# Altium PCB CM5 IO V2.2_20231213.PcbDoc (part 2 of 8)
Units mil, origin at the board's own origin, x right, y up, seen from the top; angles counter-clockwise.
Board outline 6299.61 x 3544.09 mil, 4 copper layers (Top, GND, Power, Bottom), stack 35.4 mil thick; 482 components, 404 nets, 1857 pads, 2731 vias.
Unrouted connection lines stored in the file: 1872.
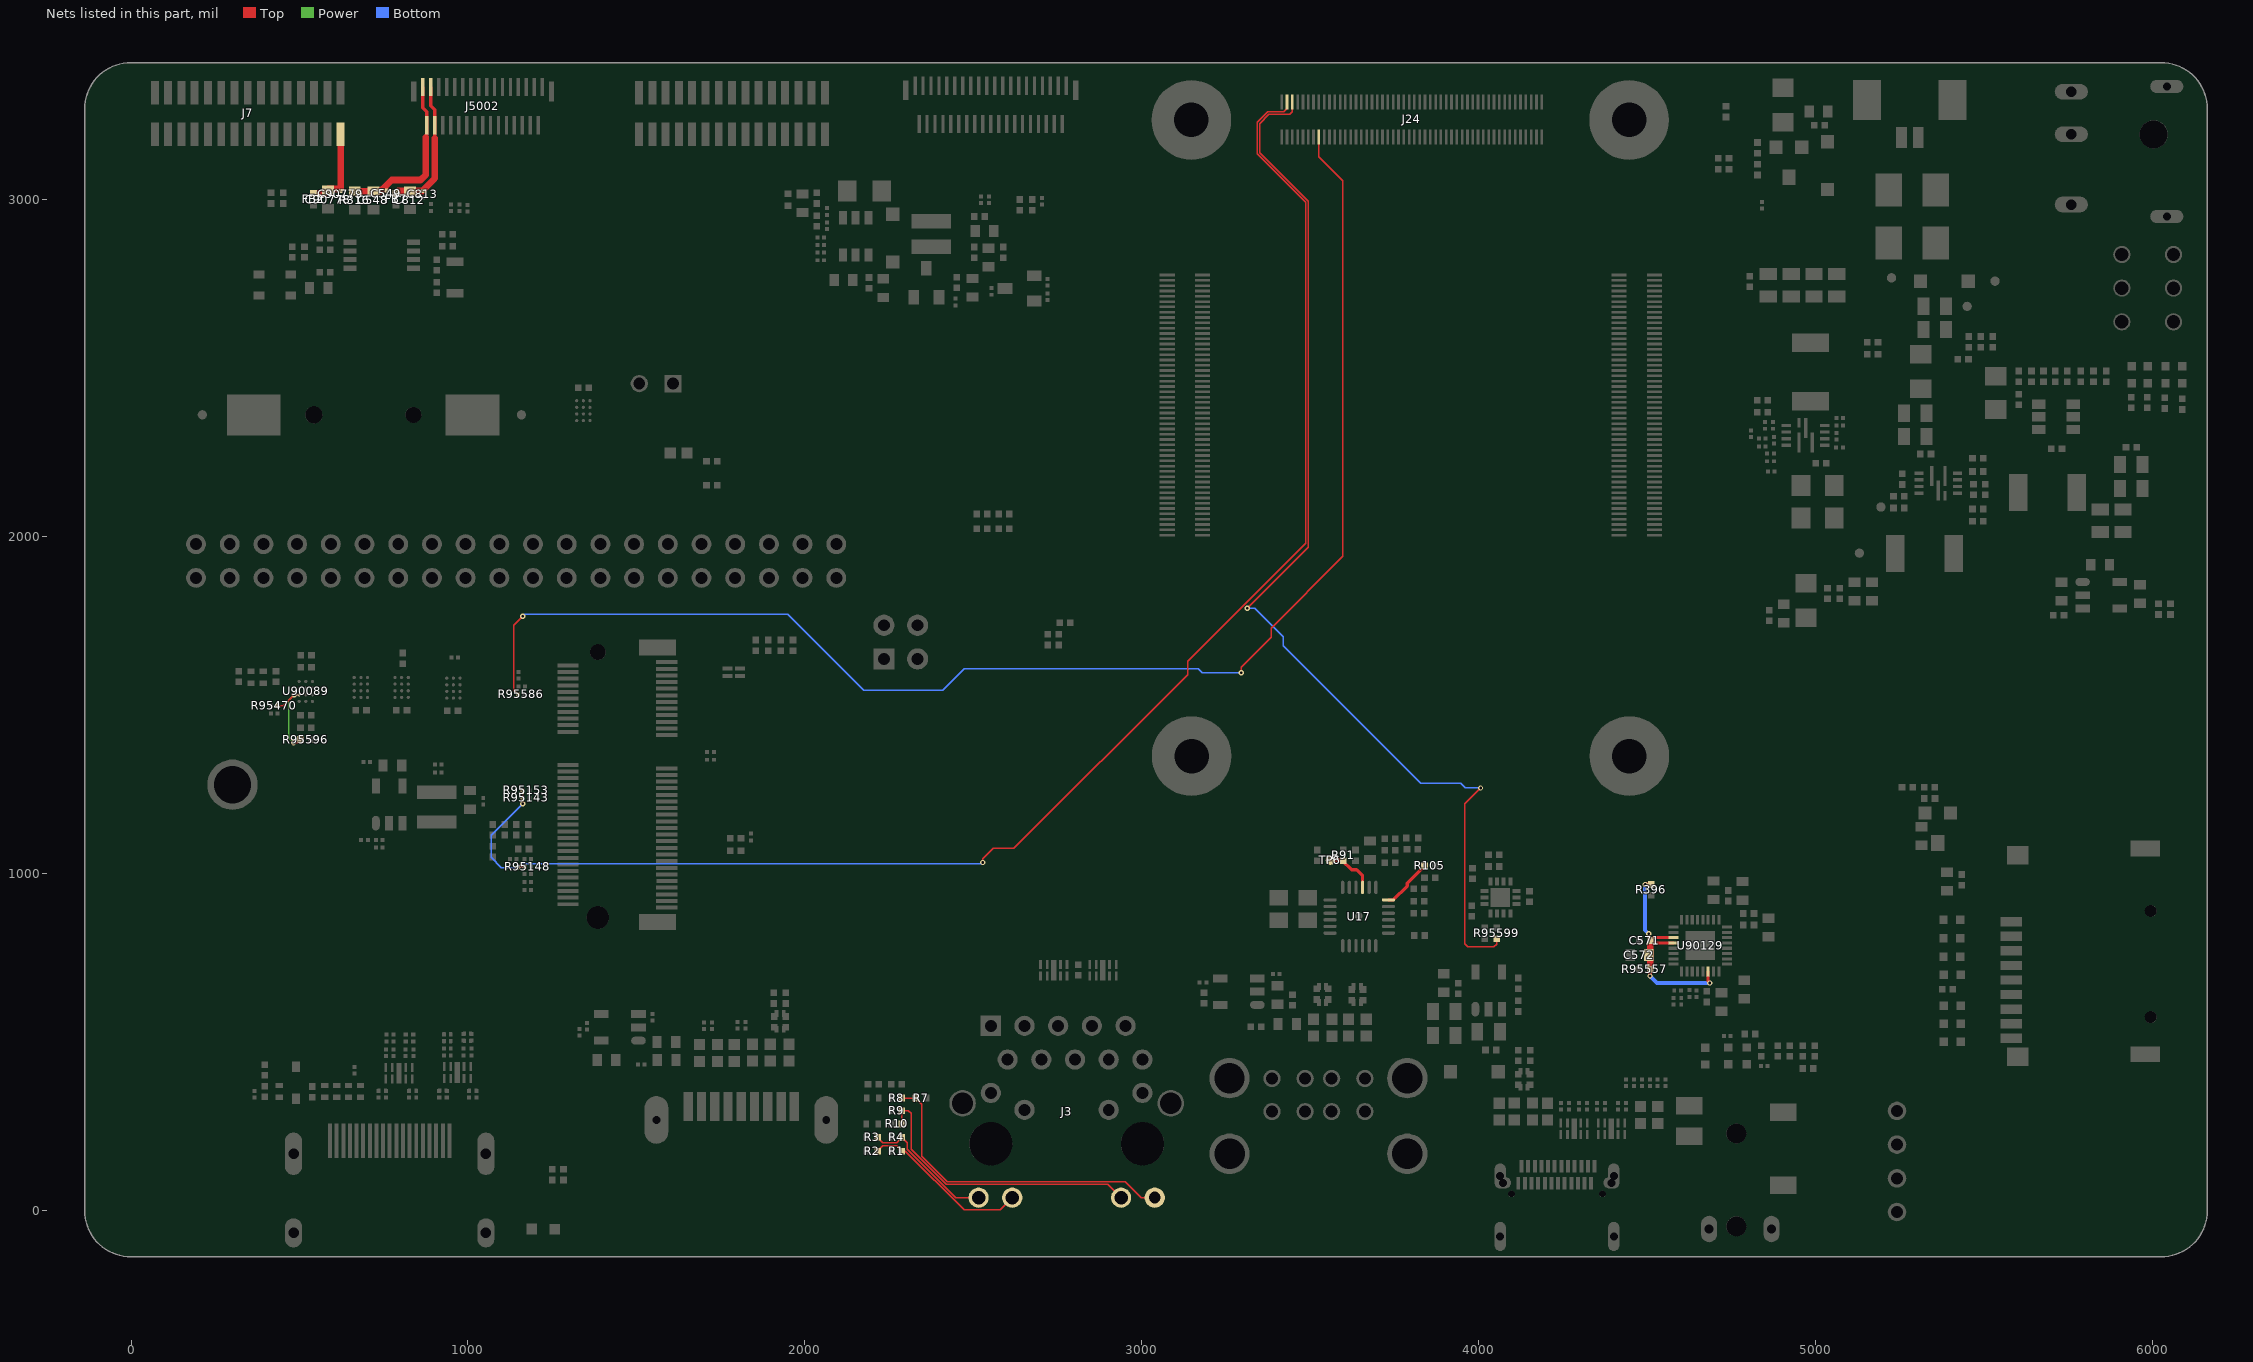
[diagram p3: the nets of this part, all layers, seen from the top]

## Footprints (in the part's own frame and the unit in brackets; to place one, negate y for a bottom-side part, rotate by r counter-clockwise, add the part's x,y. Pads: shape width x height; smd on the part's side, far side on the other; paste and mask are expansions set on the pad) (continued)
SON10_2R50X1R00X0R50 [mm]
  rect 0.2x0.675 smd: 1(-1,-0.437) 2(-0.5,-0.437) 4(0.5,-0.437) 5(1,-0.437) 6(1,0.437) 7(0.5,0.437) 9(-0.5,0.437) 10(-1,0.437)
  rect 0.4x0.775 smd: 3(0,-0.388) 8(0,0.388)
  silkscreen extent -1.46,-1.39 1.25,0.5
SOT23 [mil]
  rect 39x39 smd: 1(-38,-44.53) 2(38,-44.53)
  rect 39.37x47.24 smd: 3(0,44.53)
SOT23-6 [mm]
  rect 0.6x1 smd: 1(-0.95,-1.4) 2(0,-1.4) 3(0.95,-1.4) 4(0.95,1.4) 5(0,1.4) 6(-0.95,1.4)
  silkscreen extent -1.8,-1.9 1.5,0.8
SOT_23 [mm]
  rect 0.8x1.1 smd: 1(-0.95,-1.1) 2(0.95,-1.1) 3(0,1.1)
  silkscreen extent -1.6,-0.9 1.6,0.9
SOT_23_5 [mm]
  oval 1.1x0.6 smd: 1(-1.4,1)
  rect 1.1x0.6 smd: 2(-1.4,0) 3(-1.4,-1) 4(1.4,-1) 5(1.4,1)
  silkscreen extent -0.52,-1.5 0.55,1.5
SOT_23_6 [mm]
  rect 0.7x1 smd mask+0.05: 1(-0.95,-1.3) 2(0,-1.3) 3(0.95,-1.3) 4(0.95,1.3) 5(0,1.3) 6(-0.95,1.3)
  silkscreen extent -1.82,-1.72 1.75,0.7
TF-CKT01-009D [mm]
  rect 1.6x0.7 smd: 1(-10.516,3.2) 2(-10.516,2.1) 3(-10.516,1) 4(-10.516,-0.1) 5(-10.516,-1.2) 6(-10.516,-2.3) 7(-10.516,-3.4) 8(-10.516,-4.5) 9(-10.516,-5.6)
  rect 1.6x1.4 smd: 10(-10.016,-7) 13(-10.016,8.2)
  rect 2.2x1.2 smd: 11(-0.416,-6.8) 12(-0.416,8.7)
  round 0.9 hole 0.9 unplated: 14(0,4) 15(0,-4)
  silkscreen extent -10.52,-6.4 3.98,8.3
TP_0R70 [mm]
  round 0.7 smd: 1(0,0)
  silkscreen extent -0.45,-0.45 0.45,0.45
TYPEC-24PIN-SMD-OK [mm]
  rect 0.3x0.95 smd: A1(1.61,5.29) A2(2.11,5.29) A3(2.61,5.29) A4(3.11,5.29) A5(3.61,5.29) A6(4.11,5.29) A7(4.61,5.29) A8(5.11,5.29) A9(5.61,5.29) A10(6.11,5.29) A11(6.61,5.29) A12(7.11,5.29) B1(6.86,3.99) B2(6.36,3.99) B3(5.86,3.99) B4(5.36,3.99) B5(4.86,3.99) B6(4.36,3.99) B7(3.86,3.99) B8(3.36,3.99) B9(2.86,3.99) B10(2.36,3.99) B11(1.86,3.99) B12(1.36,3.99)
  oval 0.85x1.9 / inner oval 0.85x1.8 / far side oval 1x2.1 hole 0.6 slot 1.5 at 90 deg: E1(0,4.55) E6(8.56,4.55)
  oval 1.2x0.85 / inner oval 1.2x0.85 / far side oval 1.2x0.9 hole 0.6 slot 1 at 0 deg: E2(0.21,4.04) E5(8.38,4.04)
  oval 0.85x2.2 / inner oval 0.85x2.2 / far side oval 1x2.2 hole 0.6 slot 1.9 at 90 deg: E3(0,0)
  oval 0.85x2.2 / inner oval 0.85x2.2 / far side oval 1x2.25 hole 0.6 slot 1.9 at 90 deg: E4(8.56,0)
  round 0.5 hole 0.5: H1(0.85,3.2) H2(7.71,3.2)
  silkscreen extent -0.24,-2.35 8.87,5.55
USB30-L1 [mm]
  rect 0.7x2.2 smd: 1(-3,0) 2(-1,0) 3(1,0) 4(3,0) 5(4,0) 6(2,0) 7(0,0) 8(-2,0) 9(-4,0)
  oval 1.8x3.6 / inner oval 0.7x2.6 / far side oval 1.8x3.6 hole 0.584 slot 2.489 at 90 deg: 10(-6.4,-1) 11(6.4,-1)
  silkscreen extent -9.28,-14.64 9.29,0.92
USB_DUAL [mm]
  round 1.3 / inner round 0.9 / far side round 1.3 hole 0.9: 1(3.18,3.5) 2(3.18,1) 3(3.18,-1) 4(3.18,-3.5) 5(5.68,3.5) 6(5.68,1) 7(5.68,-1) 8(5.68,-3.5)
  round 3.048 / inner round 2.5 / far side round 3.048 hole 2.3: 9(0,6.7)
  round 3.048 / inner round 2.5 / far side round 3.048 hole 2.286: 10(0,-6.7) 11(5.7,6.7) 12(5.7,-6.7)
  silkscreen extent -9.97,-7.52 7.1,7.61
XIAO_4PIN_2D54 [mm]
  round 1.4 hole 0.9: 1(0.01,0) 2(2.55,0) 3(5.09,0) 4(7.63,0)
  silkscreen extent -1.19,-3.3 8.81,2.36

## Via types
v1: diameter 15.75, hole 7.87, Top to Bottom, 2292 vias
v2: diameter 19.68, hole 11.81, Top to Bottom, 439 vias

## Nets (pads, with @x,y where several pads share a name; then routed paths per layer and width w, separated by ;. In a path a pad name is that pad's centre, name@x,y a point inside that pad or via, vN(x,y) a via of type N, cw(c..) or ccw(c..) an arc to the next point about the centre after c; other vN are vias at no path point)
3V3_CAM1: C90778.1 C90779.1 FB2.2 J7.1 | length 256.6
  Top w11.81: C90779.1@622.05,3024.61 622.05,3030.51
  Top w19.68: FB2.2@541.34,3017.72 575.79,3017.72 C90778.1@584.65,3026.57 584.65,3030.51 622.05,3030.51 J7.1@622.05,3192.91
3V3_CAM2: C812.1 C813.1 FB7.2 J5002.28 J5002.29 | length 411
  Top w3.94: C813.1@864.17,3024.61 C813.1@866.14,3024.61
  Top w9.84: J5002.29@889.76,3332.68 889.76,3277.56 901.57,3265.75 J5002.28@901.57,3219.5 901.57,3197.5 901.57,3180.12
  Top w19.68: FB7.2@786.42,3017.72 793.31,3024.61 C812.1@827.76,3024.61 864.17,3024.61 901.57,3062.01 901.57,3180.12
5V_CAM: C548.1 C549.1 J5002.30 J5002.31 R316.2 | length 530
  Top w9.84: J5002.31@866.14,3332.68 866.14,3271.65 877.95,3259.84 J5002.30@877.95,3219.5 877.95,3187.01 875,3184.06
  Top w11.81: 740.65,3024.11 743.6,3024.11 745.08,3025.59 C549.1@757.87,3025.59
  Top w12.99: 755.91,3039.37 756.5,3039.37 757.87,3037.99 C549.1@757.87,3025.59
  Top w19.68: R316.2@663.88,3024.11 C548.1@719,3024.11 740.65,3024.11 755.91,3039.37 773.62,3057.09 859.25,3057.09 875,3072.83 875,3184.06
100M_LED_G+: J3.15 R3.2 R4.1 | length 398.3
  Top w3.94: R3.2@2215.55,216.54 2231.3,200.79 2271.65,200.79 R4.1@2287.4,216.54 2303.15,200.79 2303.15,181.47 2447.45,37.17 J3.15@2515.17,37.17
100M_LED_G-: J3.16 R1.2 R2.1 | length 499.8
  Top w3.94: R2.1@2215.55,175.2 2231.3,190.94 2271.65,190.94 R1.2@2287.4,175.2 2298.29,175.2 2472.5,0.98 2578.99,0.98 J3.16@2615.17,37.17
1000M_LED_Y+: J3.17 R9.2 R10.1 | length 859.3
  Top w3.94: R10.1@2287.4,255.91 R9.2@2287.4,295.28 2307.09,295.28 2314.96,287.4 2314.96,180.79 2418.98,76.77 2898.4,76.77 J3.17@2938.01,37.17
1000M_LED_Y-: J3.18 R7.2 R8.1 | length 963.5
  Top w3.94: R8.1@2287.4,332.68 R7.2@2328.74,332.68 2346.46,314.96 2346.46,160.43 2422.24,84.65 2949.8,84.65 2997.28,37.17 J3.18@3038.01,37.17
AVCC_1V8_CODEC_S0: C571.1 C572.1 R396.1 R95557.2 U90129.3 U90129.4 U90129.14 | length 669.2
  Top w9.06: U90129.4@4576.96,792.94 4515.13,792.94 C571.1@4507.87,800.2 4516.36,808.69 U90129.3@4576.96,808.69 ; U90129.14@4680.3,708.29 4680.3,678.95 v1(4685.04,674.21)
  Top w11.81: v1(4493.11,966.54) R396.1@4511.81,966.54 ; v1(4503.94,819.88) 4503.94,800.2 C571.1@4507.87,800.2 ; v1(4507.87,694.88) R95557.2@4507.87,714.57
  Top w19.68: C572.1@4503.94,756.89 C572.1@4507.87,756.89 ; R95557.2@4507.87,714.57 C572.1@4507.87,756.89 ; C571.1@4507.87,800.2 C572.1@4507.87,756.89
  Bottom w11.81: v1(4493.11,966.54) 4493.11,830.71 v1(4503.94,819.88) ; v1(4507.87,694.88) 4528.54,674.21 v1(4685.04,674.21)
BT_HOST_WAKE: J24.85 R95586.1 | length 4252.4
  Top w3.94: R95586.1@1148.58,1530.5 1135.83,1543.25 1135.83,1736.22 v1(1162.4,1762.8) ; v1(3294.67,1595.1) 3294.67,1611.6 3383.86,1700.79 3383.86,1727.36 3596.46,1939.96 3596.46,3055.09 3525,3126.54 J24.85@3525,3184.65
  Bottom w3.94: v1(1162.4,1762.8) 1168.31,1768.7 1948.57,1768.7 2173.96,1543.31 2408.72,1543.31 2472.69,1607.28 3166.45,1607.28 3178.63,1595.1 v1(3294.67,1595.1)
BT_REG_ON_H: J24.98 R95143.1 R95148.1 R95153.1 | length 4551.8
  Top w3.94: v1(1147.64,1016.73) 1147.64,1019.68 R95148.1@1167.28,1019.67 ; R95153.1@1162.36,1246.05 R95143.1@1162.36,1223.41 v1(1162.4,1205.71) v1(1162.4,1205.71) ; v1(2527.56,1031.5) 2527.56,1042.95 2558.59,1073.97 2620.09,1073.97 3135.54,1589.42 3135.54,1628.5 3485.63,1978.59 3485.63,2991.14 3341.54,3135.24 3341.54,3227.92 3373.46,3259.84 3420.75,3259.84 3430.51,3269.6 J24.98@3430.51,3288.58
  Bottom w3.94: v1(1162.4,1205.71) 1068.9,1112.2 1068.9,1047.24 1099.41,1016.73 v1(1147.64,1016.73) 1159.45,1028.54 2524.61,1028.54 v1(2527.56,1031.5)
BUSJ: R105.2 U17.18 | length 154.1
  Top w9.84: U17.18@3731.49,920.57 3746.25,920.57 3787.4,961.72 3787.4,970.47 R105.2@3838.58,1021.65
CC_INT0_L: J24.96 R95599.1 | length 3244
  Top w3.94: v1(3312.43,1785.87) 3493.5,1966.95 3493.5,2994.4 3349.41,3138.5 3349.41,3224.66 3376.72,3251.97 3438.98,3251.97 3446.26,3259.25 J24.96@3446.26,3288.58 ; 3966.4,781.37 3957.9,789.87 3957.9,1205.93 v1(4004.92,1252.95) ; 3966.41,781.38 4044.6,781.38 4052.78,789.56 R95599.1@4052.78,805.87
  Bottom w3.94: v1(3312.43,1785.87) 3335.19,1785.87 3419.29,1701.77 3419.29,1674.21 3826.77,1266.73 3945.87,1266.73 3959.65,1252.95 v1(4004.92,1252.95)
DRV: R91.2 TP6.1 U17.21 | length 154.4
  Top w9.84: R91.2@3597.44,1037.4 3594.98,1037.4 3622.54,1009.84 3636.81,1009.84 3654.72,991.94 U17.21@3654.72,957.97
  Top w11.81: TP6.1@3559.06,1038.39 3597.44,1038.39 R91.2@3597.44,1037.4
EINT_CTP1: R95470.1 R95596.2 U90089.C1 | length 257.9
  Top w3.94: R95470.1@435.04,1497.05 451.77,1497.05 v1(484.25,1529.53) U90089.C1@499.02,1529.53 ; v1(482.28,1386.81) 493.11,1386.81 R95596.2@502.95,1396.65
  Power w3.94: v1(482.28,1386.81) 467.52,1401.57 467.52,1512.8 v1(484.25,1529.53)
